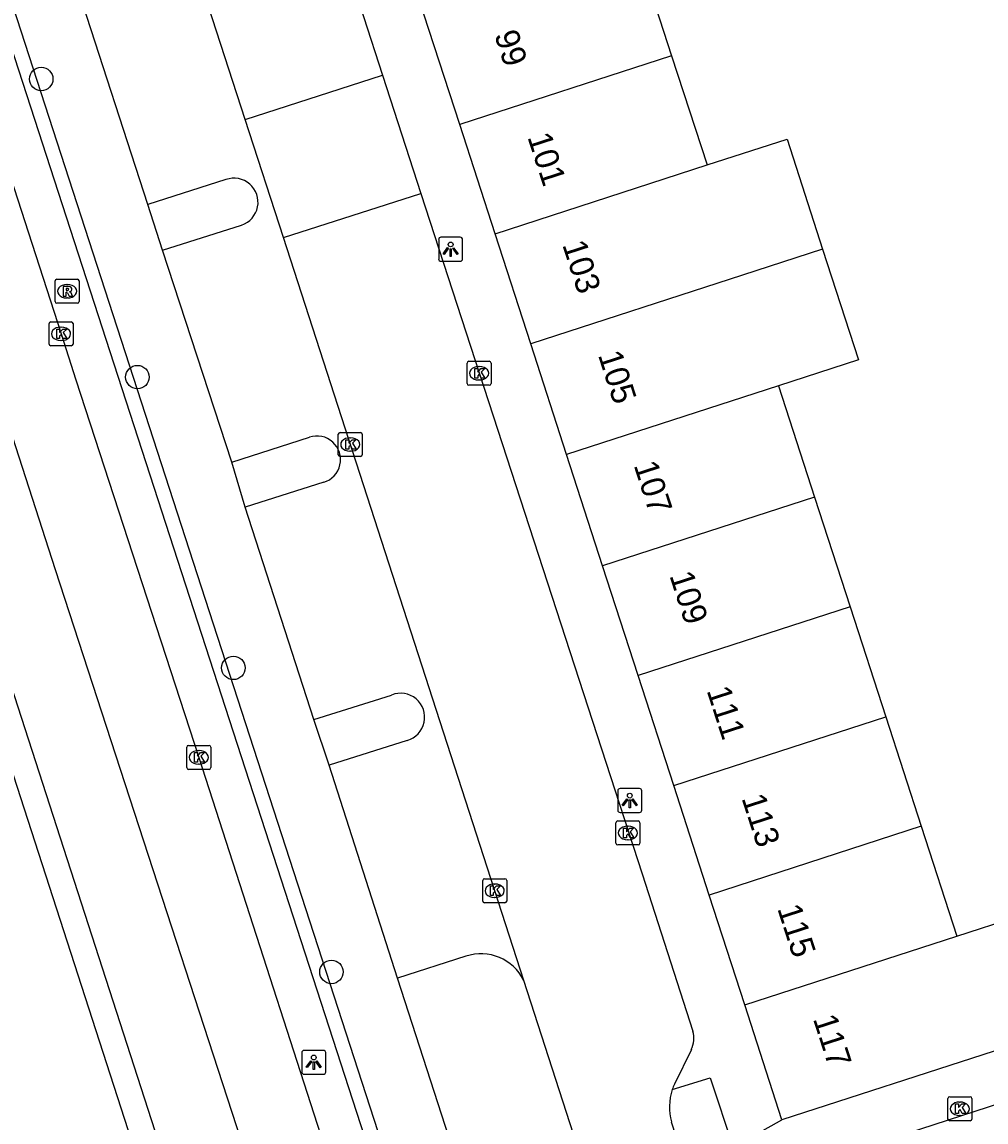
# Model space of a CAD drawing. Extents: x 159377 to 159983, y 382996 to 383595.
# Drawn here: x 159437.83 to 159478, y 383184.26 to 383230.07 of the extents above; entities that cross this region are included whole.
import ezdxf

# ---------------------------------------------------------------- set-up
doc = ezdxf.new("R2010")
doc.units = 0
for name, color, linetype in [('IMGEO_Berm_groen', 7, 'Continuous'), ('IMGEO_Boom', 7, 'Continuous'), ('IMGEO_Haag', 7, 'Continuous'), ('IMGEO_Kolk', 7, 'Continuous'), ('IMGEO_Lichtpunt', 7, 'Continuous'), ('IMGEO_Pand', 7, 'Continuous'), ('IMGEO_Pand_nummerreeks', 7, 'Continuous'), ('IMGEO_Parkeervlak_open', 7, 'Continuous'), ('IMGEO_Rijbaan_lokaal_open', 7, 'Continuous'), ('IMGEO_Rijbaan_regionaal_gesloten', 7, 'Continuous'), ('IMGEO_Rioolput', 7, 'Continuous'), ('IMGEO_Voetpad_open', 7, 'Continuous')]:
    doc.layers.add(name, color=color, linetype=linetype)

msp = doc.modelspace()

# ---------------------------------------------------------------- linework, layer by layer
at = {"layer": 'IMGEO_Berm_groen'}
for points in [[(159443.691, 383220.575), (159443.081, 383222.473)], [(159447.129, 383209.867), (159446.573, 383211.745)], [(159450.629, 383199.119), (159449.994, 383201.018)], [(159465.88, 383151.938), (159453.474, 383190.25)]]:
    msp.add_lwpolyline(points, dxfattribs=at)
at = {"layer": 'IMGEO_Boom'}
for centre in [(159438.636, 383227.698), (159442.642, 383215.284), (159446.641, 383203.172), (159450.726, 383190.51)]:
    msp.add_circle(centre, 0.489, dxfattribs=at)
at = {"layer": 'IMGEO_Haag'}
for points in [[(159410.522, 383313.711), (159410.796, 383312.64), (159412.414, 383306.629), (159413.5, 383303.035), (159430.413, 383250.521), (159435.017, 383236.267), (159472.152, 383121.826), (159491.672, 383063.465), (159493.69, 383057.889)], [(159411.104, 383313.847), (159411.376, 383312.794), (159412.992, 383306.793), (159414.072, 383303.213), (159430.983, 383250.705), (159435.589, 383236.441), (159472.722, 383122.014), (159492.238, 383063.663), (159493.793, 383059.366)]]:
    msp.add_lwpolyline(points, dxfattribs=at)
at = {"layer": 'IMGEO_Kolk'}
for p, q in [((159438.959, 383216.659), (159438.959, 383217.511)), ((159439.034, 383217.585), (159439.886, 383217.585)), ((159439.96, 383217.511), (159439.96, 383216.659)), ((159439.447, 383217.365), (159439.472, 383217.365)), ((159439.886, 383216.585), (159439.034, 383216.585)), ((159439.47, 383216.805), (159439.445, 383216.805)), ((159456.375, 383215.017), (159456.375, 383215.869)), ((159456.45, 383215.943), (159457.302, 383215.943)), ((159456.863, 383215.723), (159456.888, 383215.723)), ((159457.376, 383215.869), (159457.376, 383215.017)), ((159456.886, 383215.163), (159456.861, 383215.163)), ((159457.302, 383214.943), (159456.45, 383214.943)), ((159451.011, 383212.05), (159451.011, 383212.902)), ((159451.086, 383212.976), (159451.938, 383212.976)), ((159452.012, 383212.902), (159452.012, 383212.05)), ((159451.499, 383212.756), (159451.524, 383212.756)), ((159451.938, 383211.976), (159451.086, 383211.976)), ((159451.522, 383212.196), (159451.497, 383212.196)), ((159444.698, 383199.02), (159444.698, 383199.872)), ((159444.773, 383199.946), (159445.625, 383199.946)), ((159445.186, 383199.726), (159445.211, 383199.726)), ((159445.699, 383199.872), (159445.699, 383199.02)), ((159445.209, 383199.166), (159445.184, 383199.166)), ((159445.625, 383198.946), (159444.773, 383198.946)), ((159462.653, 383196.797), (159463.505, 383196.797)), ((159462.578, 383195.871), (159462.578, 383196.723)), ((159463.066, 383196.577), (159463.091, 383196.577)), ((159463.579, 383196.723), (159463.579, 383195.871)), ((159463.089, 383196.017), (159463.064, 383196.017)), ((159463.505, 383195.797), (159462.653, 383195.797)), ((159457.027, 383193.463), (159457.027, 383194.315)), ((159457.102, 383194.389), (159457.954, 383194.389)), ((159457.515, 383194.169), (159457.54, 383194.169)), ((159458.028, 383194.315), (159458.028, 383193.463)), ((159457.538, 383193.609), (159457.513, 383193.609)), ((159457.954, 383193.389), (159457.102, 383193.389)), ((159476.41, 383184.384), (159476.41, 383185.236)), ((159476.485, 383185.31), (159477.337, 383185.31)), ((159476.898, 383185.09), (159476.923, 383185.09)), ((159477.411, 383185.236), (159477.411, 383184.384)), ((159476.921, 383184.53), (159476.896, 383184.53)), ((159477.337, 383184.31), (159476.485, 383184.31))]:
    msp.add_line(p, q, dxfattribs=at)
for points in [[(159438.959, 383216.659), (159438.959, 383217.511)], [(159439.034, 383217.585), (159439.886, 383217.585)], [(159439.96, 383217.511), (159439.96, 383216.659)], [(159439.28, 383217.285), (159439.403, 383217.285), (159439.403, 383217.134), (159439.533, 383217.285), (159439.697, 383217.285), (159439.551, 383217.134), (159439.704, 383216.885), (159439.552, 383216.885), (159439.467, 383217.049), (159439.403, 383216.982), (159439.403, 383216.885), (159439.28, 383216.885), (159439.28, 383217.285)], [(159439.886, 383216.585), (159439.034, 383216.585)], [(159456.375, 383215.017), (159456.375, 383215.869)], [(159456.45, 383215.943), (159457.302, 383215.943)], [(159456.696, 383215.643), (159456.819, 383215.643), (159456.819, 383215.492), (159456.949, 383215.643), (159457.113, 383215.643), (159456.967, 383215.492), (159457.12, 383215.243), (159456.968, 383215.243), (159456.883, 383215.407), (159456.819, 383215.34), (159456.819, 383215.243), (159456.696, 383215.243), (159456.696, 383215.643)], [(159457.376, 383215.869), (159457.376, 383215.017)], [(159457.302, 383214.943), (159456.45, 383214.943)], [(159451.011, 383212.05), (159451.011, 383212.902)], [(159451.086, 383212.976), (159451.938, 383212.976)], [(159452.012, 383212.902), (159452.012, 383212.05)], [(159451.332, 383212.676), (159451.455, 383212.676), (159451.455, 383212.525), (159451.585, 383212.676), (159451.749, 383212.676), (159451.603, 383212.525), (159451.756, 383212.276), (159451.604, 383212.276), (159451.519, 383212.44), (159451.455, 383212.373), (159451.455, 383212.276), (159451.332, 383212.276), (159451.332, 383212.676)], [(159451.938, 383211.976), (159451.086, 383211.976)], [(159444.698, 383199.02), (159444.698, 383199.872)], [(159444.773, 383199.946), (159445.625, 383199.946)], [(159445.019, 383199.646), (159445.142, 383199.646), (159445.142, 383199.495), (159445.272, 383199.646), (159445.436, 383199.646), (159445.29, 383199.495), (159445.443, 383199.246), (159445.291, 383199.246), (159445.206, 383199.41), (159445.142, 383199.343), (159445.142, 383199.246), (159445.019, 383199.246), (159445.019, 383199.646)], [(159445.699, 383199.872), (159445.699, 383199.02)], [(159445.625, 383198.946), (159444.773, 383198.946)], [(159462.653, 383196.797), (159463.505, 383196.797)], [(159462.578, 383195.871), (159462.578, 383196.723)], [(159462.899, 383196.497), (159463.022, 383196.497), (159463.022, 383196.346), (159463.152, 383196.497), (159463.316, 383196.497), (159463.17, 383196.346), (159463.323, 383196.097), (159463.171, 383196.097), (159463.086, 383196.261), (159463.022, 383196.194), (159463.022, 383196.097), (159462.899, 383196.097), (159462.899, 383196.497)], [(159463.579, 383196.723), (159463.579, 383195.871)], [(159463.505, 383195.797), (159462.653, 383195.797)], [(159457.027, 383193.463), (159457.027, 383194.315)], [(159457.102, 383194.389), (159457.954, 383194.389)], [(159457.348, 383194.089), (159457.471, 383194.089), (159457.471, 383193.938), (159457.601, 383194.089), (159457.765, 383194.089), (159457.619, 383193.938), (159457.772, 383193.689), (159457.62, 383193.689), (159457.535, 383193.853), (159457.471, 383193.786), (159457.471, 383193.689), (159457.348, 383193.689), (159457.348, 383194.089)], [(159458.028, 383194.315), (159458.028, 383193.463)], [(159457.954, 383193.389), (159457.102, 383193.389)], [(159476.41, 383184.384), (159476.41, 383185.236)], [(159476.485, 383185.31), (159477.337, 383185.31)], [(159476.731, 383185.01), (159476.854, 383185.01), (159476.854, 383184.859), (159476.984, 383185.01), (159477.148, 383185.01), (159477.002, 383184.859), (159477.155, 383184.61), (159477.003, 383184.61), (159476.918, 383184.774), (159476.854, 383184.707), (159476.854, 383184.61), (159476.731, 383184.61), (159476.731, 383185.01)], [(159477.411, 383185.236), (159477.411, 383184.384)], [(159477.337, 383184.31), (159476.485, 383184.31)]]:
    msp.add_lwpolyline(points, dxfattribs=at)
for centre, start, end in [((159439.036, 383217.509), 91.552, 178.448), ((159439.036, 383217.509), 91.552, 178.448), ((159439.884, 383217.509), 1.552, 88.448), ((159439.884, 383217.509), 1.552, 88.448), ((159439.036, 383216.661), 181.552, 268.448), ((159439.036, 383216.661), 181.552, 268.448), ((159439.884, 383216.661), 271.552, 358.448), ((159439.884, 383216.661), 271.552, 358.448), ((159456.452, 383215.867), 91.552, 178.448), ((159456.452, 383215.867), 91.552, 178.448), ((159457.3, 383215.867), 1.552, 88.448), ((159457.3, 383215.867), 1.552, 88.448), ((159456.452, 383215.019), 181.552, 268.448), ((159456.452, 383215.019), 181.552, 268.448), ((159457.3, 383215.019), 271.552, 358.448), ((159457.3, 383215.019), 271.552, 358.448), ((159451.088, 383212.9), 91.552, 178.448), ((159451.088, 383212.9), 91.552, 178.448), ((159451.936, 383212.9), 1.552, 88.448), ((159451.936, 383212.9), 1.552, 88.448), ((159451.088, 383212.052), 181.552, 268.448), ((159451.088, 383212.052), 181.552, 268.448), ((159451.936, 383212.052), 271.552, 358.448), ((159451.936, 383212.052), 271.552, 358.448), ((159444.775, 383199.87), 91.552, 178.448), ((159444.775, 383199.87), 91.552, 178.448), ((159445.623, 383199.87), 1.552, 88.448), ((159445.623, 383199.87), 1.552, 88.448), ((159444.775, 383199.022), 181.552, 268.448), ((159444.775, 383199.022), 181.552, 268.448), ((159445.623, 383199.022), 271.552, 358.448), ((159445.623, 383199.022), 271.552, 358.448), ((159462.655, 383196.721), 91.552, 178.448), ((159462.655, 383196.721), 91.552, 178.448), ((159463.503, 383196.721), 1.552, 88.448), ((159463.503, 383196.721), 1.552, 88.448), ((159462.655, 383195.873), 181.552, 268.448), ((159462.655, 383195.873), 181.552, 268.448), ((159463.503, 383195.873), 271.552, 358.448), ((159463.503, 383195.873), 271.552, 358.448), ((159457.104, 383194.313), 91.552, 178.448), ((159457.104, 383194.313), 91.552, 178.448), ((159457.952, 383194.313), 1.552, 88.448), ((159457.952, 383194.313), 1.552, 88.448), ((159457.104, 383193.465), 181.552, 268.448), ((159457.104, 383193.465), 181.552, 268.448), ((159457.952, 383193.465), 271.552, 358.448), ((159457.952, 383193.465), 271.552, 358.448), ((159476.487, 383185.234), 91.552, 178.448), ((159476.487, 383185.234), 91.552, 178.448), ((159477.335, 383185.234), 1.552, 88.448), ((159477.335, 383185.234), 1.552, 88.448), ((159476.487, 383184.386), 181.552, 268.448), ((159476.487, 383184.386), 181.552, 268.448), ((159477.335, 383184.386), 271.552, 358.448), ((159477.335, 383184.386), 271.552, 358.448)]:
    msp.add_arc(centre, 0.0765, start, end, dxfattribs=at)
for centre, major_axis, ratio, start_param, end_param in [((159439.446, 383217.085), (-0.387, 0.002), 0.722429, 4.712389, 7.853982), ((159439.471, 383217.085), (-0.39, 0.002), 0.717154, 1.570796, 4.712389), ((159456.862, 383215.443), (-0.387, 0.002), 0.722429, 4.712389, 7.853982), ((159456.887, 383215.443), (-0.39, 0.002), 0.717154, 1.570796, 4.712389), ((159451.498, 383212.476), (-0.387, 0.002), 0.722429, 4.712389, 7.853982), ((159451.523, 383212.476), (-0.39, 0.002), 0.717154, 1.570796, 4.712389), ((159445.185, 383199.446), (-0.387, 0.002), 0.722429, 4.712389, 7.853982), ((159445.21, 383199.446), (-0.39, 0.002), 0.717154, 1.570796, 4.712389), ((159463.065, 383196.297), (-0.387, 0.002), 0.722429, 4.712389, 7.853982), ((159463.09, 383196.297), (-0.39, 0.002), 0.717154, 1.570796, 4.712389), ((159457.514, 383193.889), (-0.387, 0.002), 0.722429, 4.712389, 7.853982), ((159457.539, 383193.889), (-0.39, 0.002), 0.717154, 1.570796, 4.712389), ((159476.897, 383184.81), (-0.387, 0.002), 0.722429, 4.712389, 7.853982), ((159476.922, 383184.81), (-0.39, 0.002), 0.717154, 1.570796, 4.712389)]:
    msp.add_ellipse(centre, major_axis=major_axis, ratio=ratio, start_param=start_param, end_param=end_param, dxfattribs=at)
at = {"layer": 'IMGEO_Lichtpunt'}
for p, q in [((159456.096, 383221.105), (159455.288, 383221.105)), ((159456.096, 383221.105), (159455.288, 383221.105)), ((159455.194, 383221.01), (159455.194, 383220.203)), ((159455.194, 383221.01), (159455.194, 383220.203)), ((159456.19, 383220.203), (159456.19, 383221.01)), ((159456.19, 383220.203), (159456.19, 383221.01)), ((159455.288, 383220.109), (159456.096, 383220.109)), ((159455.288, 383220.109), (159456.096, 383220.109)), ((159463.56, 383198.15), (159462.752, 383198.15)), ((159463.56, 383198.15), (159462.752, 383198.15)), ((159462.658, 383198.055), (159462.658, 383197.248)), ((159462.658, 383198.055), (159462.658, 383197.248)), ((159463.654, 383197.248), (159463.654, 383198.055)), ((159463.654, 383197.248), (159463.654, 383198.055)), ((159462.752, 383197.154), (159463.56, 383197.154)), ((159462.752, 383197.154), (159463.56, 383197.154)), ((159449.491, 383187.149), (159449.491, 383186.342)), ((159449.491, 383187.149), (159449.491, 383186.342)), ((159450.393, 383187.244), (159449.585, 383187.244)), ((159450.393, 383187.244), (159449.585, 383187.244)), ((159450.487, 383186.342), (159450.487, 383187.149)), ((159450.487, 383186.342), (159450.487, 383187.149)), ((159449.585, 383186.248), (159450.393, 383186.248)), ((159449.585, 383186.248), (159450.393, 383186.248))]:
    msp.add_line(p, q, dxfattribs=at)
for points in [[(159455.568, 383220.674), (159455.607, 383220.646), (159455.419, 383220.384), (159455.381, 383220.411), (159455.568, 383220.674)], [(159455.67, 383220.626), (159455.717, 383220.626), (159455.717, 383220.304), (159455.67, 383220.304), (159455.67, 383220.626)], [(159455.78, 383220.646), (159455.818, 383220.673), (159456.005, 383220.411), (159455.966, 383220.383), (159455.78, 383220.646)], [(159463.032, 383197.719), (159463.071, 383197.691), (159462.883, 383197.429), (159462.845, 383197.456), (159463.032, 383197.719)], [(159463.244, 383197.691), (159463.282, 383197.718), (159463.469, 383197.456), (159463.43, 383197.428), (159463.244, 383197.691)], [(159463.134, 383197.671), (159463.181, 383197.671), (159463.181, 383197.349), (159463.134, 383197.349), (159463.134, 383197.671)], [(159449.865, 383186.813), (159449.904, 383186.785), (159449.716, 383186.523), (159449.678, 383186.55), (159449.865, 383186.813)], [(159449.967, 383186.765), (159450.014, 383186.765), (159450.014, 383186.443), (159449.967, 383186.443), (159449.967, 383186.765)], [(159450.077, 383186.785), (159450.115, 383186.812), (159450.302, 383186.55), (159450.263, 383186.522), (159450.077, 383186.785)]]:
    msp.add_lwpolyline(points, dxfattribs=at)
for centre in [(159455.693, 383220.808), (159463.157, 383197.853), (159449.99, 383186.947)]:
    msp.add_circle(centre, 0.0994, dxfattribs=at)
for centre, start, end in [((159455.288, 383221.01), 90, 180), ((159455.288, 383221.01), 90, 180), ((159456.096, 383221.01), 0, 90), ((159456.096, 383221.01), 0, 90), ((159455.288, 383220.203), 180, 270), ((159455.288, 383220.203), 180, 270), ((159456.096, 383220.203), 270, 0), ((159456.096, 383220.203), 270, 360), ((159462.752, 383198.055), 90, 180), ((159462.752, 383198.055), 90, 180), ((159463.56, 383198.055), 0, 90), ((159463.56, 383198.055), 0, 90), ((159462.752, 383197.248), 180, 270), ((159462.752, 383197.248), 180, 270), ((159463.56, 383197.248), 270, 0), ((159463.56, 383197.248), 270, 360), ((159449.585, 383187.149), 90, 180), ((159449.585, 383187.149), 90, 180), ((159450.393, 383187.149), 0, 90), ((159450.393, 383187.149), 0, 90), ((159449.585, 383186.342), 180, 270), ((159449.585, 383186.342), 180, 270), ((159450.393, 383186.342), 270, 0), ((159450.393, 383186.342), 270, 360)]:
    msp.add_arc(centre, 0.0946, start, end, dxfattribs=at)
at = {"layer": 'IMGEO_Pand'}
for points in [[(159463.412, 383233.26), (159464.901, 383228.664)], [(159456.069, 383225.801), (159454.58, 383230.397)], [(159464.901, 383228.664), (159456.069, 383225.801)], [(159464.901, 383228.664), (159466.374, 383224.117)], [(159457.542, 383221.254), (159456.069, 383225.801)], [(159466.374, 383224.117), (159469.708, 383225.198), (159471.192, 383220.612)], [(159457.542, 383221.254), (159466.374, 383224.117)], [(159459.027, 383216.669), (159457.542, 383221.254)], [(159471.192, 383220.612), (159467.859, 383219.532), (159459.027, 383216.669)], [(159471.192, 383220.612), (159472.685, 383215.997), (159469.354, 383214.917)], [(159460.523, 383212.053), (159459.027, 383216.669)], [(159469.354, 383214.917), (159460.523, 383212.053)], [(159469.354, 383214.917), (159470.854, 383210.284)], [(159462.023, 383207.421), (159460.523, 383212.053)], [(159470.854, 383210.284), (159462.023, 383207.421)], [(159470.854, 383210.284), (159472.334, 383205.716)], [(159463.503, 383202.854), (159462.023, 383207.421)], [(159472.334, 383205.716), (159463.503, 383202.854)], [(159472.334, 383205.716), (159473.82, 383201.131)], [(159464.988, 383198.268), (159463.503, 383202.854)], [(159464.988, 383198.268), (159473.82, 383201.131)], [(159473.82, 383201.131), (159475.296, 383196.574)], [(159466.465, 383193.711), (159464.988, 383198.268)], [(159475.296, 383196.574), (159466.465, 383193.711)], [(159475.296, 383196.574), (159476.779, 383191.997)], [(159467.947, 383189.134), (159466.465, 383193.711)], [(159476.779, 383191.997), (159479.269, 383192.804), (159480.817, 383188.02)], [(159467.947, 383189.134), (159476.779, 383191.997)], [(159469.497, 383184.351), (159467.947, 383189.134)], [(159480.817, 383188.02), (159478.331, 383187.21), (159469.497, 383184.351)]]:
    msp.add_lwpolyline(points, dxfattribs=at)
at = {"layer": 'IMGEO_Parkeervlak_open'}
for points in [[(159443.081, 383222.473), (159440.202, 383231.342)], [(159446.33, 383223.509), (159443.081, 383222.473)], [(159443.691, 383220.575), (159446.984, 383221.615)], [(159446.573, 383211.745), (159443.691, 383220.575)], [(159446.573, 383211.745), (159449.806, 383212.778)], [(159450.404, 383210.901), (159447.129, 383209.867)], [(159449.994, 383201.018), (159447.129, 383209.867)], [(159449.994, 383201.018), (159453.234, 383202.043)], [(159453.886, 383200.151), (159450.629, 383199.119)], [(159453.474, 383190.25), (159450.629, 383199.119)], [(159456.328, 383191.165), (159453.474, 383190.25)]]:
    msp.add_lwpolyline(points, dxfattribs=at)
for centre, radius, start, end in [((159446.667, 383222.565), 1.002, 288.4564, 109.6433), ((159450.121, 383211.845), 0.985, 286.6688, 108.6743), ((159453.61, 383201.114), 1.002, 285.9998, 112.029), ((159456.954, 383189.277), 1.989, 26.2525, 108.3525)]:
    msp.add_arc(centre, radius, start, end, dxfattribs=at)
at = {"layer": 'IMGEO_Rijbaan_lokaal_open'}
for points in [[(159425.699, 383311.777), (159436.697, 383277.841), (159445.705, 383250), (159448.834, 383240.286), (159449.683, 383237.65), (159452.856, 383227.855)], [(159447.133, 383226.011), (159443.055, 383238.609), (159439.368, 383250), (159423.364, 383299.1)], [(159447.133, 383226.011), (159452.856, 383227.855)], [(159452.856, 383227.855), (159454.449, 383222.936)], [(159448.725, 383221.092), (159447.133, 383226.011)], [(159448.725, 383221.092), (159454.449, 383222.936)], [(159454.449, 383222.936), (159463.673, 383194.598), (159465.784, 383188.044)], [(159458.738, 383190.157), (159448.725, 383221.092)], [(159466.746, 383165.416), (159458.738, 383190.157)], [(159465.721, 383187.273), (159465.021, 383185.842)], [(159465.45, 383182.548), (159464.9, 383184.26)]]:
    msp.add_lwpolyline(points, dxfattribs=at)
for centre, radius, start, end in [((159464.733, 383187.742), 1.093, 334.6073, 16.0499), ((159467.309, 383184.787), 2.52, 155.246, 160.9824), ((159467.055, 383184.891), 2.245, 161.3818, 196.3232)]:
    msp.add_arc(centre, radius, start, end, dxfattribs=at)
at = {"layer": 'IMGEO_Rijbaan_regionaal_gesloten'}
for points in [[(159502.129, 383022.731), (159491.02, 383051.068), (159484.52, 383069.071), (159473.222, 383102.578), (159461.474, 383138.586), (159449.876, 383174.543), (159439.228, 383207.25), (159430.293, 383234.905), (159427.53, 383243.457), (159415.383, 383281.415), (159405.034, 383314.472), (159401.734, 383327.224), (159398.985, 383340.227), (159396.636, 383352.03), (159394.586, 383364.232), (159392.136, 383379.485), (159391.102, 383386.058)], [(159481.958, 383059.184), (159480.897, 383062.863), (159477.465, 383074.388), (159474.861, 383082.723), (159471.482, 383093.553), (159456.598, 383139.574), (159432.844, 383213.007), (159426.147, 383233.702), (159420.872, 383250), (159392.563, 383337.471), (159379.438, 383378.025)], [(159405.305, 383327.063), (159407.402, 383318.032), (159409.091, 383311.769), (159411.115, 383305.269), (159412.518, 383300.689), (159415.124, 383292.413), (159421.088, 383273.781), (159427.134, 383255.214), (159428.816, 383250), (159433.13, 383236.631), (159433.397, 383235.806), (159439.459, 383217.085), (159440.075, 383215.172), (159445.199, 383199.446), (159451.824, 383178.924), (159457.544, 383161.294), (159463.853, 383141.727), (159476.503, 383102.624), (159482.981, 383083.113), (159484.902, 383077.49), (159489.07, 383065.601), (159491.374, 383059.121), (159493.294, 383053.824)], [(159404.584, 383303.68), (159421.962, 383250), (159427.145, 383233.992), (159433.835, 383213.326), (159457.577, 383139.944), (159472.482, 383093.792), (159476.1, 383082.988), (159478.912, 383074.803), (159482.846, 383063.588), (159484.186, 383059.948)]]:
    msp.add_lwpolyline(points, dxfattribs=at)
at = {"layer": 'IMGEO_Rioolput'}
for p, q in [((159439.213, 383218.434), (159439.213, 383219.286)), ((159439.288, 383219.36), (159440.14, 383219.36)), ((159440.214, 383219.286), (159440.214, 383218.434)), ((159439.701, 383219.14), (159439.726, 383219.14)), ((159440.14, 383218.36), (159439.288, 383218.36)), ((159439.724, 383218.58), (159439.699, 383218.58))]:
    msp.add_line(p, q, dxfattribs=at)
for points in [[(159439.213, 383218.434), (159439.213, 383219.286)], [(159439.288, 383219.36), (159440.14, 383219.36)], [(159440.214, 383219.286), (159440.214, 383218.434)], [(159439.802, 383219.058), (159439.55, 383219.06), (159439.55, 383218.66)], [(159439.55, 383218.66), (159439.674, 383218.66), (159439.674, 383218.822), (159439.685, 383218.822)], [(159439.728, 383218.979), (159439.674, 383218.979), (159439.674, 383218.898)], [(159439.674, 383218.898), (159439.726, 383218.898)], [(159439.732, 383218.793), (159439.803, 383218.66), (159439.943, 383218.66), (159439.878, 383218.786)], [(159440.14, 383218.36), (159439.288, 383218.36)]]:
    msp.add_lwpolyline(points, dxfattribs=at)
for centre, radius, start, end in [((159439.29, 383219.284), 0.0765, 91.552, 178.448), ((159439.29, 383219.284), 0.0765, 91.552, 178.448), ((159440.138, 383219.284), 0.0765, 1.552, 88.448), ((159440.138, 383219.284), 0.0765, 1.552, 88.448), ((159439.684, 383218.769), 0.0533, 26.0293, 88.6989), ((159439.71, 383219.087), 0.19, 274.7715, 282.9687), ((159439.734, 383218.883), 0.0964, 77.0061, 93.1865), ((159439.748, 383218.94), 0.0378, 276.6634, 79.6772), ((159439.801, 383218.948), 0.109, 350.3612, 89.416), ((159439.799, 383218.948), 0.112, 277.5842, 350.9817), ((159439.783, 383218.733), 0.108, 29.5134, 73.7905), ((159439.29, 383218.436), 0.0765, 181.552, 268.448), ((159439.29, 383218.436), 0.0765, 181.552, 268.448), ((159440.138, 383218.436), 0.0765, 271.552, 358.448), ((159440.138, 383218.436), 0.0765, 271.552, 358.448)]:
    msp.add_arc(centre, radius, start, end, dxfattribs=at)
for centre, major_axis, ratio, start_param, end_param in [((159439.7, 383218.86), (-0.387, 0.002), 0.722429, 4.712389, 7.853982), ((159439.725, 383218.86), (-0.39, 0.002), 0.717154, 1.570796, 4.712389)]:
    msp.add_ellipse(centre, major_axis=major_axis, ratio=ratio, start_param=start_param, end_param=end_param, dxfattribs=at)
at = {"layer": 'IMGEO_Voetpad_open'}
for points in [[(159464.927, 383185.608), (159466.499, 383186.102), (159467.461, 383183.208)], [(159470.835, 383180.219), (159470.155, 383182.307), (159480.969, 383185.822), (159483.158, 383184.208)], [(159467.461, 383183.208), (159469.497, 383184.351)]]:
    msp.add_lwpolyline(points, dxfattribs=at)

# ---------------------------------------------------------------- texts
at = {"layer": 'IMGEO_Pand_nummerreeks'}
for s, rotation, p in [('99', 287.9503, (159457.503, 383229.549)), ('101', 287.9503, (159458.884, 383225.286)), ('103', 287.9503, (159460.337, 383220.801)), ('105', 287.9506, (159461.825, 383216.207)), ('107', 287.9503, (159463.313, 383211.615)), ('109', 287.9503, (159464.801, 383207.022)), ('111', 287.9503, (159466.352, 383202.234)), ('113', 287.9503, (159467.806, 383197.748)), ('115', 287.9503, (159469.294, 383193.154)), ('117', 287.9503, (159470.782, 383188.561))]:
    msp.add_text(s, height=1, rotation=rotation, dxfattribs=at).set_placement(p)

doc.saveas('drawing.dxf')
